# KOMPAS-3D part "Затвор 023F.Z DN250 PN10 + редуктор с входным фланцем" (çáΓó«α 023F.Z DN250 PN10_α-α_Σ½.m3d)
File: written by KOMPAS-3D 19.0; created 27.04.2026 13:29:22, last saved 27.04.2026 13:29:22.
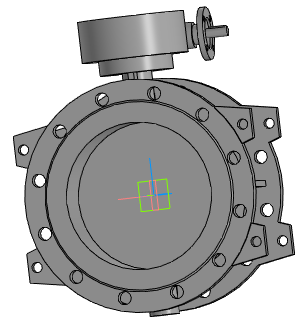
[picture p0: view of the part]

Document properties: Полное имя файла: ..\..\Затвор 023F.Z DN200-DN1600_редуктор с входным фланцем\Затвор 023F.Z DN250 PN10 + редуктор с входным фланцем.a3d

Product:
- Part/product: Затвор 023F.Z DN250 PN10 + редуктор с входным фланцем
    Масса: 74.3407

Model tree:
1. Операция без истории:1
